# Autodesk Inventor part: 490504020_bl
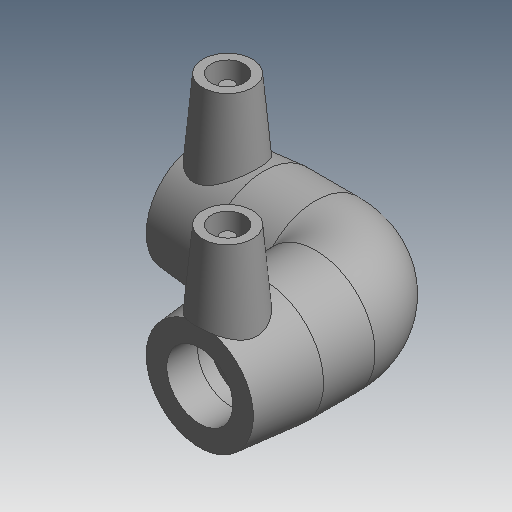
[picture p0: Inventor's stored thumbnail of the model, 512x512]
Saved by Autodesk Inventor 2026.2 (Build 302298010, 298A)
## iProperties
Created: 2017-06
Part Number: 490504020_bl
Material: Generic
Description: PLASSON 90° ELBOW 20
Document SubType Name: Modeling
Designer: KIM
Mass: 55.0731 g
Surface Area: 148.067 cm^2
Volume: 55.0731 cm^3
Density: 1 g/cm^3
Appearance: Default
Author: KIM
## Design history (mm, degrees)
derived "490504 -20-75.ipt"
feature "Solid1::490504 -20-75.ipt" dims "ScaleForDerivedMember" = 10
tag "TaggingFeature1"
body "Solid1"
other parameters: "d2" = 36 [user parameter], "d4" = 19.41176 [user parameter], "d5" = 32.4 [user parameter], "d8" = 168 deg [user parameter], "d10" = 14 [user parameter], "d11" = 4.66667 [user parameter], "d14" = 17.6296 [user parameter], "d19" = 3.52592 [user parameter], "d20" = 168 deg [user parameter], "d22" = 33.12 [user parameter], "d23" = 36 [user parameter], "d24" = 32.1264 [user parameter], "d29" = 38 [user parameter], "d30" = 15 [user parameter], "d31" = 39.6 [user parameter], "d34" = 5 deg [user parameter], "d35" = 15 [user parameter], "d39" = 5 deg [user parameter], "d41" = 4 [user parameter], "d42" = 14 [user parameter], "d43" = 0 [user parameter], "d45" = 4 [user parameter], "d46" = 14 [user parameter], "d47" = 0 [user parameter], "d50" = 17 [user parameter], "d51" = 14 [user parameter], "d52" = 35 [user parameter], "d54" = 90 deg [user parameter], "d67" = 45 deg [user parameter], "d71" = 90 deg [user parameter], "d75" = 1.8 [user parameter], "d82" = 45 deg [user parameter], "d83" = 35 [user parameter], "d84" = 32.4 [user parameter], "d87" = 90 deg [user parameter], "d90" = 35 [user parameter], "d91" = 0 [user parameter], "d92" = 35 [user parameter], "d93" = 0 [user parameter], "d94" = 90 deg [user parameter], "d101" = 3 [user parameter], "d102" = 0 [user parameter], "d103" = 3 [user parameter], "d104" = 0 [user parameter], "d105" = 10.15 [user parameter], "d106" = 2.5375 [user parameter], "d110" = 19.25 [user parameter], "d111" = 66 [user parameter], "d112" = 66 [user parameter], "d113" = 66 [user parameter], "d114" = 66 [user parameter], "L_" = 66 [user parameter], "L_1" = 35 [user parameter], "D_" = 36 [user parameter], "A_" = 38 [user parameter], "d_2" = 12 [user parameter]
